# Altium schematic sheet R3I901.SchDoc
size A4
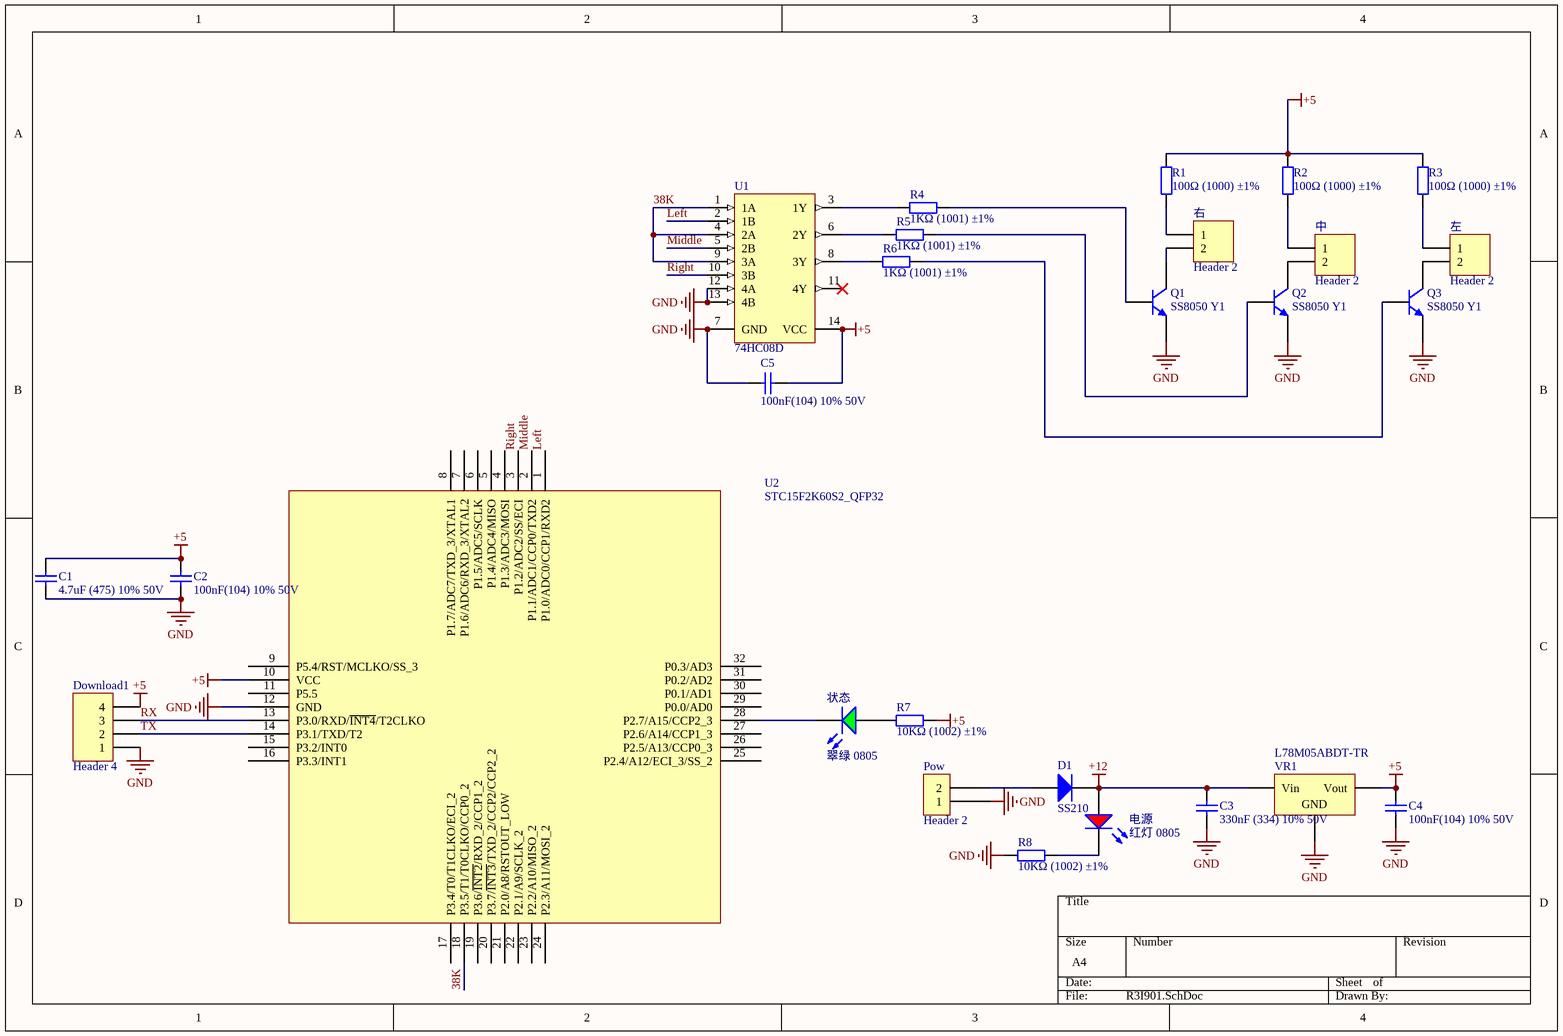
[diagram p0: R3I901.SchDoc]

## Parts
C1  4.7uF (475) 10% 50V  [LC-1206_C]
C2  100nF(104) 10% 50V  [LC-0805_C]
C3  330nF (334) 10% 50V  [LC-0805_C]
C4  100nF(104) 10% 50V  [LC-0805_C]
C5  100nF(104) 10% 50V  [LC-0805_C]
D1  SS210  [LC-SMA(DO-214AC)_S1]
Download1  Header 4  [HDR1X4]
Pow  Header 2  [VH-2A - Circle Hole]
Q1  SS8050 Y1  [LC-SOT-23(SOT-23-3)]
Q2  SS8050 Y1  [LC-SOT-23(SOT-23-3)]
Q3  SS8050 Y1  [LC-SOT-23(SOT-23-3)]
R1  100Ω (1000) ±1%  [LC-0805_R]
R2  100Ω (1000) ±1%  [LC-0805_R]
R3  100Ω (1000) ±1%  [LC-0805_R]
R4  1KΩ (1001) ±1%  [LC-0805_R]
R5  1KΩ (1001) ±1%  [LC-0805_R]
R6  1KΩ (1001) ±1%  [LC-0805_R]
R7  10KΩ (1002) ±1%  [LC-0805_R]
R8  10KΩ (1002) ±1%  [LC-0805_R]
U1  74HC08D  [LC-SOIC-14_150mil]
U2  STC15F2K60S2_QFP32  [LQFP32]
VR1  L78M05ABDT-TR  [LC-TO-252-2-180]
中  Header 2  [HDR1X2]
右  Header 2  [HDR1X2]
左  Header 2  [HDR1X2]
状态  翠绿 0805  [LC-0805_LED_S1]
电源  红灯 0805  [LC-0805_LED_S1]

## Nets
+5: C1.2 C2.2 C4.2 C5.1 Download1.4 R1.2 R2.2 R3.2 R7.1 U1.14(VCC) U2.10(VCC) VR1.3(Vout)
+12: C3.2 D1.2(K) VR1.1(Vin) 电源.A
GND: C1.1 C2.1 C3.1 C4.1 C5.2 Download1.1 Pow.1 Q1.2(E) Q2.2(E) Q3.2(E) R8.1 U1.7(GND) U1.12(4A) U1.13(4B) U2.12(GND) VR1.2(GND)
38K: U1.1(1A) U1.4(2A) U1.9(3A) U2.18(P3.5/T1/T0CLKO/CCP0_2)
Left: U1.2(1B) U2.1(P1.0/ADC0/CCP1/RXD2)
Middle: U1.5(2B) U2.2(P1.1/ADC1/CCP0/TXD2)
Right: U1.10(3B) U2.3(P1.2/ADC2/SS/ECI)
RX: Download1.3 U2.13(P3.0/RXD/~{INT4}/T2CLKO)
TX: Download1.2 U2.14(P3.1/TXD/T2)
NetD1_1: D1.1(A) Pow.2
NetQ1_1: Q1.1(B) R4.2
NetQ1_3: Q1.3(C) 右.2
NetQ2_1: Q2.1(B) R5.2
NetQ2_3: Q2.3(C) 中.2
NetQ3_1: Q3.1(B) R6.2
NetQ3_3: Q3.3(C) 左.2
NetR1_1: R1.1 右.1
NetR2_1: R2.1 中.1
NetR3_1: R3.1 左.1
NetR4_1: R4.1 U1.3(1Y)
NetR5_1: R5.1 U1.6(2Y)
NetR6_1: R6.1 U1.8(3Y)
NetR7_2: R7.2 状态.A
NetR8_2: R8.2 电源.K
NetU2_28: U2.28(P2.7/A15/CCP2_3) 状态.K

Not connected (* = marked no-connect by the designer): U1 11(4Y)*; U2 4(P1.3/ADC3/MOSI) 5(P1.4/ADC4/MISO) 6(P1.5/ADC5/SCLK) 7(P1.6/ADC6/RXD_3/XTAL2) 8(P1.7/ADC7/TXD_3/XTAL1) 9(P5.4/RST/MCLKO/SS_3) 11(P5.5) 15(P3.2/INT0) 16(P3.3/INT1) 17(P3.4/T0/T1CLKO/ECI_2) 19(P3.6/~{INT2}/RXD_2/CCP1_2) 20(P3.7/~{INT3}/TXD_2/CCP2/CCP2_2) 21(P2.0/A8/RSTOUT_LOW) 22(P2.1/A9/SCLK_2) 23(P2.2/A10/MISO_2) 24(P2.3/A11/MOSI_2) 25(P2.4/A12/ECI_3/SS_2) 26(P2.5/A13/CCP0_3) 27(P2.6/A14/CCP1_3) 29(P0.0/AD0) 30(P0.1/AD1) 31(P0.2/AD2) 32(P0.3/AD3)

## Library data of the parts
C1 = 1206 4.7uF (475) 10% 50V: 贴片电容
C2 C4 C5 = 0805 100nF(104) 10% 50V: 贴片电容
C3 = 0805 330nF (334) 10% 50V: 贴片电容
D1 = SMA(DO-214AC) SS210: 二极管
Download1 = Header 4: Header, 4-Pin
Pow = Header 2: 贴片2p座
Q1-Q3 = SOT-23 SS8050 Y1: 三极管
R1-R3 = 0805 100Ω (1000) 1%: 贴片电阻
R4-R6 = 0805 1KΩ (1001) 1%: 贴片电阻
R7 R8 = 0805 10KΩ (1002) 1%: 贴片电阻
U1 = 74HC08D: 74系列逻辑芯片
VR1 = TO-252-2 L78M05ABDT-TR: 低压差线性稳压(LDO)
中 右 左 = Header 2: Header, 2-Pin
状态 = 0805 翠绿: 发光二极管
电源 = 0805 红灯: 发光二极管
